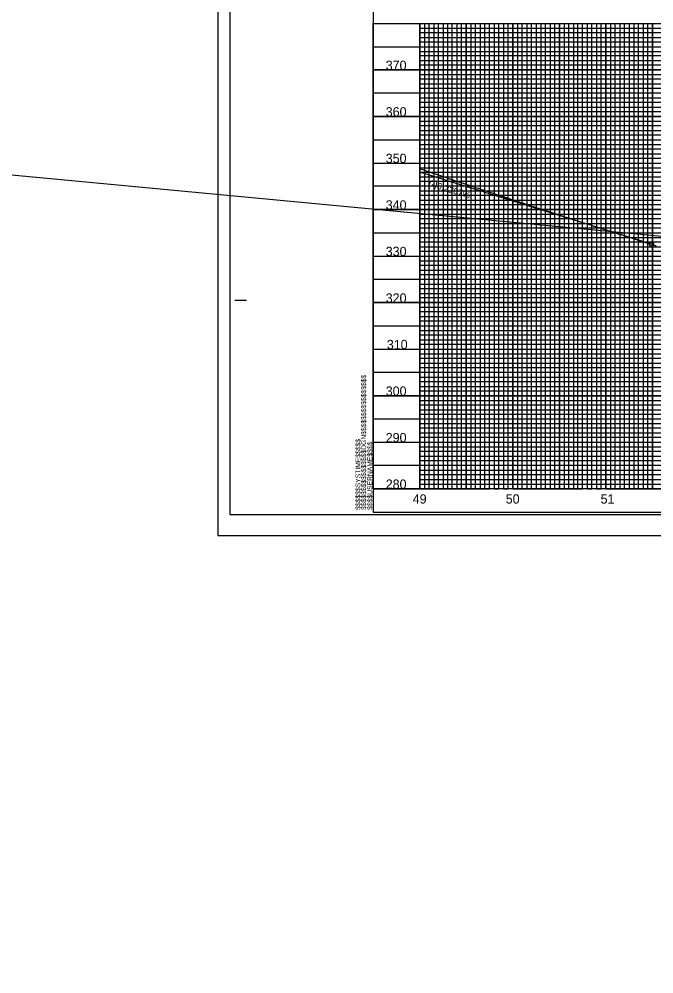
# Model space of a CAD drawing. Extents: x 571503 to 593215, y -77195 to -51828.
# Drawn here: x 583403 to 584085, y -54155 to -53129 of the extents above; entities that cross this region are included whole.
import ezdxf

# ---------------------------------------------------------------- set-up
doc = ezdxf.new("R2010")
doc.units = 0
for name, color, linetype in [('Default', 7, 'Continuous'), ('Exist Vertical Profile Horizontal Axis Label Major', 7, 'Continuous'), ('Exist Vertical Profile Vertical Axis Label', 7, 'Continuous'), ('Prop PFL Text', 7, 'Continuous'), ('Prop Vertical Profile Curve Label', 7, 'Continuous'), ('Prop Vertical Profile Grade', 7, 'Continuous'), ('Prop Vertical Profile Grade Label', 7, 'Continuous'), ('Prop VPI Label', 7, 'Continuous'), ('Sheet Clip Boundary CELL', 7, 'Continuous'), ('Sheet DOT Grid CELL', 7, 'Continuous'), ('Sheet Plot Border Inside CELL', 7, 'Continuous'), ('Sheet Plot Border Outside CELL', 7, 'Continuous'), ('Sheet Profile CELL', 7, 'Continuous'), ('Sheet Profile Grid Major CELL', 7, 'Continuous'), ('Sheet Profile Grid Middle CELL', 7, 'Continuous'), ('Sheet Profile Grid Minor CELL', 7, 'Continuous')]:
    doc.layers.add(name, color=color, linetype=linetype)

msp = doc.modelspace()

# ---------------------------------------------------------------- linework, layer by layer
at = {"layer": 'Default'}
msp.add_line((583783.2, -53633.7), (583833.2, -53633.7), dxfattribs=at)
at = {"layer": 'Prop PFL Text'}
msp.add_line((571620.7, -52186.3), (592499.5, -54154.9), dxfattribs=at)
at = {"layer": 'Prop Vertical Profile Curve Label'}
msp.add_circle((584082.2, -53370.9), 2.25, dxfattribs=at)
at = {"layer": 'Prop Vertical Profile Grade'}
msp.add_line((584082.2, -53370.9), (584087.2, -53372.5), dxfattribs=at)
msp.add_spline([(583833.2, -53289.7), (583833.8, -53289.9), (583844.6, -53293.6), (583855.4, -53297.2), (583866.2, -53300.9), (583877, -53304.5), (583887.8, -53308.1), (583898.6, -53311.7), (583909.4, -53315.3), (583920.2, -53318.9), (583931, -53322.5), (583941.8, -53326), (583952.6, -53329.6), (583963.4, -53333.1), (583974.2, -53336.6), (583985, -53340.1), (583995.8, -53343.6), (584006.6, -53347.1), (584017.4, -53350.5), (584028.2, -53354), (584039, -53357.4), (584049.8, -53360.8), (584060.6, -53364.2), (584071.4, -53367.6), (584082.2, -53370.9)], degree=3, dxfattribs=at)
at = {"layer": 'Prop VPI Label'}
msp.add_line((584082.2, -53370.9), (583833.2, -53293.5), dxfattribs=at)
at = {"layer": 'Sheet Clip Boundary CELL'}
msp.add_lwpolyline([(583833.2, -53133.7), (585233.2, -53133.7), (585233.2, -53633.7), (583833.2, -53633.7)], close=True, dxfattribs=at)
at = {"layer": 'Sheet DOT Grid CELL'}
for p, q in [((583783.2, -53633.7), (583783.2, -53133.7)), ((583783.2, -53133.7), (585283.1, -53133.7)), ((583833.2, -53633.7), (583833.2, -53133.7)), ((583833.2, -53133.7), (583833.2, -53633.7)), ((583883.2, -53633.7), (583883.2, -53133.7)), ((583883.2, -53133.7), (583883.2, -53633.7)), ((583933.2, -53633.7), (583933.2, -53133.7)), ((583933.2, -53133.7), (583933.2, -53633.7)), ((583983.2, -53633.7), (583983.2, -53133.7)), ((583983.2, -53133.7), (583983.2, -53633.7)), ((584033.2, -53633.7), (584033.2, -53133.7)), ((584033.2, -53133.7), (584033.2, -53633.7)), ((584083.2, -53633.7), (584083.2, -53133.7)), ((584083.2, -53133.7), (584083.2, -53633.7)), ((583783.2, -53183.7), (585283.2, -53183.7)), ((583783.2, -53183.7), (585283.1, -53183.7)), ((583783.2, -53233.7), (585283.2, -53233.7)), ((583783.2, -53233.7), (585283.1, -53233.7)), ((583783.2, -53283.7), (585283.2, -53283.7)), ((583783.2, -53283.7), (585283.1, -53283.7)), ((583783.2, -53333.7), (585283.2, -53333.7)), ((583783.2, -53333.7), (585283.1, -53333.7)), ((583783.2, -53383.7), (585283.2, -53383.7)), ((583783.2, -53383.7), (585283.1, -53383.7)), ((583783.2, -53433.7), (585283.2, -53433.7)), ((583783.2, -53433.7), (585283.1, -53433.7)), ((583783.2, -53483.7), (585283.2, -53483.7)), ((583783.2, -53483.7), (585283.1, -53483.7)), ((583783.2, -53533.7), (585283.2, -53533.7)), ((583783.2, -53533.7), (585283.1, -53533.7)), ((583783.2, -53583.7), (585283.2, -53583.7)), ((583783.2, -53583.7), (585283.1, -53583.7))]:
    msp.add_line(p, q, dxfattribs=at)
at = {"layer": 'Sheet Plot Border Inside CELL'}
msp.add_lwpolyline([(583629.2, -53661.2), (585295.7, -53661.2), (585295.7, -52606.1), (583629.2, -52606.1)], close=True, dxfattribs=at)
at = {"layer": 'Sheet Plot Border Outside CELL'}
msp.add_lwpolyline([(583616.2, -53683.7), (585300.2, -53683.7), (585300.2, -52583.7), (583616.2, -52583.7)], close=True, dxfattribs=at)
at = {"layer": 'Sheet Profile CELL'}
for p, q in [((583616.2, -52583.7), (583616.2, -53683.7)), ((583783.2, -53133.7), (585283.2, -53133.7)), ((583634.7, -53431.2), (583647.2, -53431.2)), ((585283.2, -53633.7), (583783.2, -53633.7)), ((583783.2, -53658.7), (585283.2, -53658.7)), ((583783.2, -53658.7), (583783.2, -53658.7)), ((583783.2, -53658.7), (583783.2, -53658.7)), ((583783.2, -53658.7), (583783.2, -53658.7)), ((583783.2, -53658.7), (583783.2, -53658.7)), ((583783.2, -53658.7), (583783.2, -53658.7)), ((583783.2, -53658.7), (583783.2, -53658.7)), ((583783.2, -53658.7), (583783.2, -53658.7)), ((583616.2, -53683.7), (585300.2, -53683.7))]:
    msp.add_line(p, q, dxfattribs=at)
msp.add_lwpolyline([(585283.2, -52608.7), (583783.2, -52608.7), (583783.2, -53658.7), (585283.2, -53658.7)], close=True, dxfattribs=at)
msp.add_lwpolyline([(583820.7, -53658.7), (583820.7, -53658.7)], dxfattribs=at)
at = {"layer": 'Sheet Profile Grid Major CELL'}
msp.add_line((583783.2, -53633.7), (583783.2, -53633.7), dxfattribs=at)
for points in [[(583833.2, -53133.7), (583833.2, -53633.7), (583883.2, -53633.7), (583883.2, -53133.7), (583933.2, -53133.7), (583933.2, -53633.7), (583983.2, -53633.7), (583983.2, -53133.7), (584033.2, -53133.7), (584033.2, -53633.7), (584083.2, -53633.7), (584083.2, -53133.7), (584133.2, -53133.7)], [(585283.2, -53183.7), (583783.2, -53183.7)], [(585283.2, -53233.7), (583783.2, -53233.7), (583783.2, -53283.7), (585283.2, -53283.7)], [(585283.2, -53333.7), (583783.2, -53333.7), (583783.2, -53383.7), (585283.2, -53383.7)], [(585283.2, -53433.7), (583783.2, -53433.7), (583783.2, -53483.7), (585283.2, -53483.7)], [(585283.2, -53533.7), (583783.2, -53533.7), (583783.2, -53533.7), (583783.2, -53583.7), (585283.2, -53583.7)], [(585283.2, -53633.7), (583783.2, -53633.7)]]:
    msp.add_lwpolyline(points, dxfattribs=at)
at = {"layer": 'Sheet Profile Grid Middle CELL'}
for points in [[(583808.2, -53133.7), (583858.2, -53133.7), (583858.2, -53633.7), (583908.2, -53633.7), (583908.2, -53133.7), (583958.2, -53133.7), (583958.2, -53633.7), (584008.2, -53633.7), (584008.2, -53133.7), (584058.2, -53133.7), (584058.2, -53633.7), (584108.2, -53633.7)], [(583783.2, -53158.7), (585283.2, -53158.7)], [(585283.2, -53208.7), (583783.2, -53208.7), (583783.2, -53258.7), (585283.2, -53258.7)], [(585283.2, -53308.7), (583783.2, -53308.7), (583783.2, -53358.7), (585283.2, -53358.7)], [(585283.2, -53408.7), (583783.2, -53408.7), (583783.2, -53458.7), (585283.2, -53458.7)], [(585283.2, -53508.7), (583783.2, -53508.7), (583783.2, -53558.7), (585283.2, -53558.7)], [(585283.2, -53608.7), (583783.2, -53608.7)]]:
    msp.add_lwpolyline(points, dxfattribs=at)
at = {"layer": 'Sheet Profile Grid Minor CELL'}
for p, q in [((583833.2, -53138.7), (585233.2, -53138.7)), ((585233.2, -53143.7), (583833.2, -53143.7)), ((583833.2, -53148.7), (585233.2, -53148.7)), ((585233.2, -53153.7), (583833.2, -53153.7)), ((583833.2, -53163.7), (585233.2, -53163.7)), ((585233.2, -53168.7), (583833.2, -53168.7)), ((583833.2, -53173.7), (585233.2, -53173.7)), ((585233.2, -53178.7), (583833.2, -53178.7)), ((583833.2, -53188.7), (585233.2, -53188.7)), ((585233.2, -53193.7), (583833.2, -53193.7)), ((583833.2, -53198.7), (585233.2, -53198.7)), ((585233.2, -53203.7), (583833.2, -53203.7)), ((583833.2, -53213.7), (585233.2, -53213.7)), ((585233.2, -53218.7), (583833.2, -53218.7)), ((583833.2, -53223.7), (585233.2, -53223.7)), ((585233.2, -53228.7), (583833.2, -53228.7)), ((583833.2, -53238.7), (585233.2, -53238.7)), ((585233.2, -53243.7), (583833.2, -53243.7)), ((583833.2, -53248.7), (585233.2, -53248.7)), ((585233.2, -53253.7), (583833.2, -53253.7)), ((583833.2, -53263.7), (585233.2, -53263.7)), ((585233.2, -53268.7), (583833.2, -53268.7)), ((583833.2, -53273.7), (585233.2, -53273.7)), ((585233.2, -53278.7), (583833.2, -53278.7)), ((583833.2, -53288.7), (585233.2, -53288.7)), ((585233.2, -53293.7), (583833.2, -53293.7)), ((583833.2, -53298.7), (585233.2, -53298.7)), ((585233.2, -53303.7), (583833.2, -53303.7)), ((583833.2, -53313.7), (585233.2, -53313.7)), ((585233.2, -53318.7), (583833.2, -53318.7)), ((583833.2, -53323.7), (585233.2, -53323.7)), ((585233.2, -53328.7), (583833.2, -53328.5)), ((583833.2, -53338.7), (585233.2, -53338.7)), ((585233.2, -53343.7), (583833.2, -53343.7)), ((583833.2, -53348.7), (585233.2, -53348.7)), ((585233.2, -53353.7), (583833.2, -53353.7)), ((583833.2, -53363.7), (585233.2, -53363.7)), ((585233.2, -53368.7), (583833.2, -53368.7)), ((583833.2, -53373.7), (585233.2, -53373.7)), ((585233.2, -53378.7), (583833.2, -53378.7)), ((583833.2, -53388.7), (585233.2, -53388.7)), ((585233.2, -53393.7), (583833.2, -53393.7)), ((583833.2, -53398.7), (585233.2, -53398.7)), ((585233.2, -53403.7), (583833.2, -53403.7)), ((583833.2, -53413.7), (585233.2, -53413.7)), ((585233.2, -53418.7), (583833.2, -53418.7)), ((583833.2, -53423.7), (585233.2, -53423.7)), ((585233.2, -53428.7), (583833.2, -53428.7)), ((583833.2, -53438.7), (585233.2, -53438.7)), ((585233.2, -53443.7), (583833.2, -53443.7)), ((583833.2, -53448.7), (585233.2, -53448.7)), ((585233.2, -53453.7), (583833.2, -53453.7)), ((583833.2, -53463.7), (585233.2, -53463.7)), ((585233.2, -53468.7), (583833.2, -53468.7)), ((583833.2, -53473.7), (585233.2, -53473.7)), ((585233.2, -53478.7), (583833.2, -53478.7)), ((583833.2, -53488.7), (585233.2, -53488.7)), ((585233.2, -53493.7), (583833.2, -53493.7)), ((583833.2, -53498.7), (585233.2, -53498.7)), ((585233.2, -53503.7), (583833.2, -53503.7)), ((583833.2, -53513.7), (585233.2, -53513.7)), ((585233.2, -53518.7), (583833.2, -53518.7)), ((583833.2, -53523.7), (585233.2, -53523.7)), ((585233.2, -53528.7), (583833.2, -53528.7)), ((583833.2, -53538.7), (585233.2, -53538.7)), ((585233.2, -53543.7), (583833.2, -53543.7)), ((583833.2, -53548.7), (585233.2, -53548.7)), ((585233.2, -53553.7), (583833.2, -53553.7)), ((583833.2, -53563.7), (585233.2, -53563.7)), ((585233.2, -53568.7), (583833.2, -53568.7)), ((583833.2, -53573.7), (585233.2, -53573.7)), ((585233.2, -53578.7), (583833.2, -53578.7)), ((583833.2, -53588.7), (585233.2, -53588.7)), ((585233.2, -53593.7), (583833.2, -53593.7)), ((583833.2, -53598.7), (585233.2, -53598.7)), ((585233.2, -53603.7), (583833.2, -53603.7)), ((583833.2, -53613.7), (585233.2, -53613.7)), ((585233.2, -53618.7), (583833.2, -53618.7)), ((583833.2, -53623.7), (585233.2, -53623.7)), ((583833.2, -53628.7), (585233.2, -53628.7))]:
    msp.add_line(p, q, dxfattribs=at)
for points in [[(583833.2, -53133.7), (583838.2, -53133.7), (583838.2, -53633.7), (583843.2, -53633.7), (583843.2, -53133.7), (583848.2, -53133.7), (583848.2, -53633.7), (583853.2, -53633.7), (583853.2, -53133.7), (583863.2, -53133.7), (583863.2, -53633.7), (583868.2, -53633.7), (583868.2, -53133.7), (583873.2, -53133.7), (583873.2, -53633.7), (583878.2, -53633.7), (583888.2, -53633.7), (583893.2, -53633.7), (583893.2, -53133.7), (583898.2, -53133.7), (583898.2, -53633.7), (583903.2, -53633.7), (583903.2, -53133.7), (583913.2, -53133.7), (583913.2, -53633.7), (583918.2, -53633.7), (583918.2, -53133.7), (583923.2, -53133.7), (583923.2, -53633.7), (583928.2, -53633.7), (583928.2, -53133.7), (583938.2, -53133.7), (583938.2, -53633.7), (583943.2, -53633.7), (583943.2, -53133.7), (583948.2, -53133.7), (583948.2, -53633.7), (583953.2, -53633.7), (583953.2, -53133.7), (583963.2, -53133.7), (583963.2, -53633.7), (583968.2, -53633.7), (583968.2, -53133.7), (583973.2, -53133.7), (583973.2, -53633.7), (583978.2, -53633.7), (583978.2, -53133.7), (583988.2, -53133.7), (583988.2, -53633.7), (583993.2, -53633.7), (583993.2, -53133.7), (583998.2, -53133.7), (583998.2, -53633.7), (584003.2, -53633.7), (584003.2, -53133.7), (584013.2, -53133.7), (584013.2, -53633.7), (584018.2, -53633.7), (584018.2, -53133.7), (584023.2, -53133.7), (584023.2, -53633.7), (584028.2, -53633.7), (584028.2, -53133.7), (584038.2, -53133.7), (584038.2, -53633.7), (584043.2, -53633.7), (584043.2, -53133.7), (584048.2, -53133.7), (584048.2, -53633.7)], [(583878.2, -53633.7), (583878.2, -53133.7), (583888.2, -53133.7), (583888.2, -53633.7)], [(584048.2, -53633.7), (584053.2, -53633.7), (584053.2, -53133.7), (584063.2, -53133.7), (584063.2, -53633.7), (584068.2, -53633.7), (584068.2, -53133.7), (584073.2, -53133.7), (584073.2, -53633.7), (584078.2, -53633.7), (584078.2, -53133.7), (584088.2, -53133.7)]]:
    msp.add_lwpolyline(points, dxfattribs=at)

# ---------------------------------------------------------------- texts
at = {"layer": 'Exist Vertical Profile Horizontal Axis Label Major'}
for s, p in [('49', (583825.7, -53649.6)), ('50', (583925.6, -53649.6)), ('51', (584027.5, -53649.6))]:
    msp.add_text(s, height=10, dxfattribs=at).set_placement(p)
at = {"layer": 'Exist Vertical Profile Vertical Axis Label'}
for s, p in [('370', (583796.7, -53183.7)), ('360', (583796.7, -53233.7)), ('350', (583796.7, -53283.7)), ('340', (583796.7, -53333.7)), ('330', (583796.7, -53383.7)), ('330', (583796.7, -53383.7)), ('320', (583796.7, -53433.7)), ('320', (583796.7, -53433.7)), ('310', (583797.9, -53483.7)), ('310', (583797.9, -53483.7)), ('300', (583796.7, -53533.7)), ('300', (583796.7, -53533.7)), ('290', (583796.7, -53583.7)), ('290', (583796.7, -53583.7)), ('280', (583796.7, -53633.7)), ('280', (583796.7, -53633.7))]:
    msp.add_text(s, height=10, dxfattribs=at).set_placement(p)
at = {"layer": 'Prop Vertical Profile Grade Label'}
msp.add_text('(-)6.2207%', height=7, rotation=342.7225, dxfattribs=at).set_placement((583842.1, -53308.4))
at = {"layer": 'Sheet Profile CELL'}
for s, p in [('$$$$$$$$$$$$$$$$DGN$$$$$$$$$$$$$$$$', (583775.6, -53656.3)), ('$$$$$$SYSTIME$$$$$', (583769.5, -53656.3)), ('$$$$USERNAME$$$$', (583782.2, -53656.3))]:
    msp.add_text(s, height=5.25, rotation=90, dxfattribs=at).set_placement(p)

doc.saveas('drawing.dxf')
